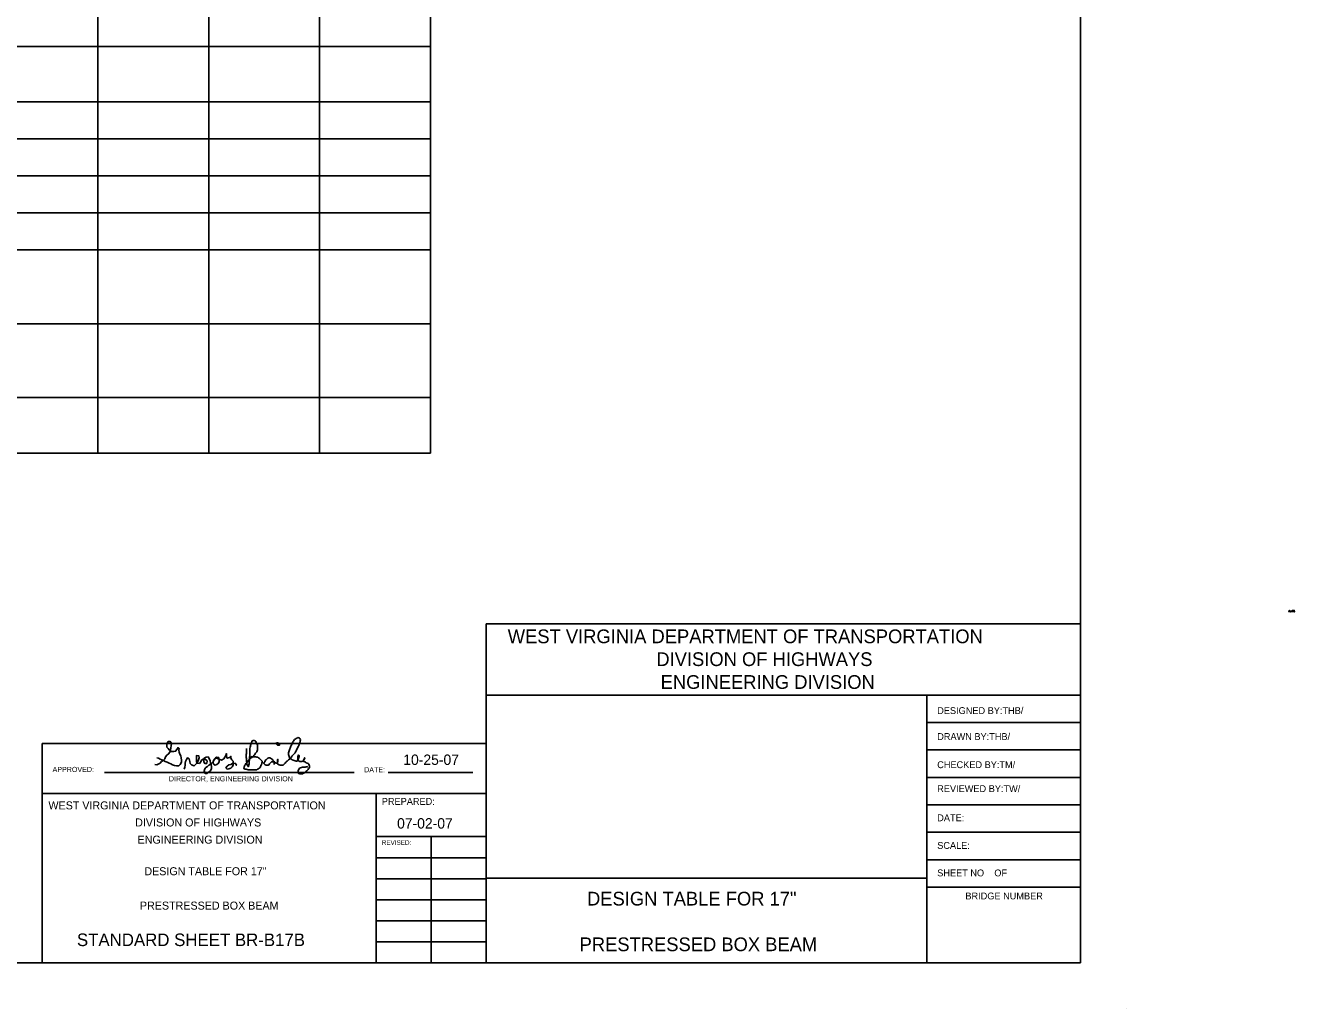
# Model space of a CAD drawing. Extents: x 762.3 to 791.9, y -1210.3 to -1192.2.
# Drawn here: x 780.44 to 791.88, y -1210.35 to -1201.48 of the extents above; entities that cross this region are included whole.
import ezdxf

# ---------------------------------------------------------------- set-up
doc = ezdxf.new("R2010")
doc.units = 0
doc.layers.add('Default', color=7, linetype='Continuous')
doc.layers.add('Level 1', color=7, linetype='Continuous')

msp = doc.modelspace()

# ---------------------------------------------------------------- linework, layer by layer
at = {"layer": 'Default'}
for p, q in [((789.954, -1192.61), (789.954, -1209.935)), ((781.091, -1202.169), (781.091, -1201.169)), ((782.091, -1202.169), (782.091, -1201.169)), ((783.091, -1202.169), (783.091, -1201.169)), ((784.091, -1202.169), (784.091, -1201.169)), ((764.508, -1201.669), (784.091, -1201.669)), ((764.508, -1202.169), (784.091, -1202.169)), ((781.091, -1205.336), (781.091, -1202.169)), ((782.091, -1205.336), (782.091, -1202.169)), ((783.091, -1205.336), (783.091, -1202.169)), ((784.091, -1205.336), (784.091, -1202.169)), ((766.258, -1202.502), (784.091, -1202.502)), ((766.258, -1202.836), (784.091, -1202.836)), ((764.508, -1203.169), (784.091, -1203.169)), ((766.258, -1203.502), (784.091, -1203.502)), ((766.258, -1204.169), (784.091, -1204.169)), ((764.508, -1204.836), (784.091, -1204.836)), ((764.508, -1205.336), (784.091, -1205.336)), ((789.954, -1206.875), (784.592, -1206.875)), ((784.592, -1206.875), (784.592, -1209.935)), ((784.592, -1206.941), (784.592, -1206.941)), ((789.954, -1206.941), (789.954, -1206.941)), ((788.568, -1207.519), (784.592, -1207.519)), ((788.568, -1207.519), (788.568, -1209.935)), ((789.954, -1207.519), (788.568, -1207.519)), ((789.954, -1207.766), (788.568, -1207.766)), ((784.592, -1207.955), (780.59, -1207.955)), ((780.59, -1207.955), (780.59, -1209.935)), ((784.592, -1207.955), (784.592, -1207.955)), ((789.954, -1208.014), (788.568, -1208.014)), ((781.152, -1208.216), (783.402, -1208.216)), ((783.71, -1208.216), (784.473, -1208.216)), ((789.954, -1208.261), (788.568, -1208.261)), ((783.602, -1208.408), (780.59, -1208.408)), ((783.602, -1208.408), (783.602, -1209.935)), ((784.592, -1208.408), (783.602, -1208.408)), ((789.954, -1208.509), (788.568, -1208.509)), ((784.592, -1208.796), (783.602, -1208.796)), ((784.097, -1208.796), (784.097, -1209.935)), ((789.954, -1208.756), (788.568, -1208.756)), ((784.592, -1208.986), (783.602, -1208.986)), ((789.954, -1209.004), (788.568, -1209.004)), ((784.592, -1209.176), (783.602, -1209.176)), ((788.568, -1209.169), (784.592, -1209.169)), ((789.954, -1209.251), (788.568, -1209.251)), ((784.592, -1209.365), (783.602, -1209.365)), ((784.592, -1209.555), (783.602, -1209.555)), ((784.592, -1209.745), (783.602, -1209.745)), ((789.954, -1209.935), (763.554, -1209.935)), ((784.592, -1209.935), (784.592, -1209.935)), ((784.592, -1209.935), (784.592, -1209.935)), ((789.954, -1209.911), (789.954, -1209.911)), ((789.954, -1209.935), (789.954, -1209.935)), ((790.367, -1210.347), (790.367, -1210.347))]:
    msp.add_line(p, q, dxfattribs=at)
at = {"layer": 'Level 1'}
for points in [[(791.83, -1206.764), (791.831, -1206.764), (791.831, -1206.764), (791.832, -1206.764), (791.832, -1206.763), (791.833, -1206.763), (791.834, -1206.762), (791.834, -1206.762), (791.834, -1206.761), (791.835, -1206.76), (791.835, -1206.76), (791.836, -1206.759), (791.836, -1206.758), (791.836, -1206.758), (791.836, -1206.757), (791.836, -1206.756), (791.835, -1206.756), (791.835, -1206.757), (791.834, -1206.757), (791.834, -1206.758), (791.835, -1206.759), (791.835, -1206.759), (791.836, -1206.76), (791.837, -1206.76), (791.837, -1206.76), (791.838, -1206.759), (791.838, -1206.758), (791.839, -1206.759), (791.838, -1206.759), (791.839, -1206.76), (791.839, -1206.761), (791.839, -1206.761), (791.839, -1206.762), (791.839, -1206.763), (791.839, -1206.763), (791.839, -1206.764), (791.838, -1206.765), (791.838, -1206.765), (791.837, -1206.764), (791.836, -1206.764), (791.836, -1206.764), (791.835, -1206.764), (791.834, -1206.763), (791.834, -1206.763), (791.833, -1206.763), (791.833, -1206.763), (791.832, -1206.762), (791.831, -1206.762), (791.831, -1206.762)], [(791.84, -1206.766), (791.841, -1206.765), (791.841, -1206.764), (791.841, -1206.764), (791.841, -1206.763), (791.841, -1206.762), (791.842, -1206.762), (791.842, -1206.762), (791.842, -1206.763), (791.842, -1206.764), (791.843, -1206.764), (791.844, -1206.765), (791.844, -1206.764), (791.845, -1206.764), (791.845, -1206.763), (791.845, -1206.763), (791.846, -1206.762), (791.845, -1206.761), (791.845, -1206.761), (791.845, -1206.762), (791.845, -1206.762), (791.845, -1206.763), (791.845, -1206.764), (791.846, -1206.764), (791.846, -1206.763), (791.846, -1206.763), (791.847, -1206.762), (791.848, -1206.762), (791.848, -1206.763), (791.848, -1206.764), (791.848, -1206.764), (791.847, -1206.763), (791.847, -1206.763), (791.847, -1206.762), (791.848, -1206.762), (791.849, -1206.762), (791.849, -1206.762), (791.849, -1206.763), (791.85, -1206.764), (791.85, -1206.764), (791.85, -1206.765), (791.85, -1206.766), (791.849, -1206.766), (791.849, -1206.767), (791.848, -1206.767), (791.848, -1206.767), (791.847, -1206.766), (791.848, -1206.766), (791.848, -1206.765), (791.848, -1206.765), (791.849, -1206.764), (791.85, -1206.764), (791.85, -1206.763), (791.851, -1206.763), (791.851, -1206.762), (791.852, -1206.762), (791.852, -1206.762), (791.853, -1206.762), (791.853, -1206.763), (791.852, -1206.764), (791.852, -1206.764), (791.851, -1206.764), (791.851, -1206.764), (791.85, -1206.763), (791.851, -1206.763), (791.851, -1206.762), (791.852, -1206.762), (791.853, -1206.762), (791.853, -1206.763), (791.854, -1206.762), (791.855, -1206.762), (791.855, -1206.761), (791.855, -1206.76), (791.855, -1206.761), (791.855, -1206.761), (791.855, -1206.762), (791.856, -1206.762), (791.857, -1206.761), (791.857, -1206.761), (791.857, -1206.762), (791.857, -1206.763), (791.857, -1206.763), (791.857, -1206.764), (791.857, -1206.764), (791.857, -1206.765), (791.857, -1206.765), (791.856, -1206.766), (791.855, -1206.766), (791.855, -1206.765), (791.855, -1206.765), (791.856, -1206.764), (791.857, -1206.764), (791.857, -1206.764), (791.858, -1206.764), (791.859, -1206.764), (791.859, -1206.764)], [(791.862, -1206.759), (791.862, -1206.759), (791.862, -1206.759), (791.862, -1206.76), (791.862, -1206.76), (791.862, -1206.76), (791.862, -1206.761), (791.862, -1206.761), (791.862, -1206.761), (791.862, -1206.762), (791.862, -1206.762), (791.862, -1206.762), (791.862, -1206.763), (791.862, -1206.763), (791.862, -1206.763), (791.862, -1206.764), (791.862, -1206.764), (791.862, -1206.764), (791.863, -1206.765), (791.863, -1206.765), (791.863, -1206.765), (791.863, -1206.764), (791.863, -1206.764), (791.863, -1206.764), (791.863, -1206.763), (791.863, -1206.763), (791.863, -1206.763), (791.863, -1206.762), (791.863, -1206.762), (791.863, -1206.762), (791.863, -1206.761), (791.863, -1206.761), (791.863, -1206.761), (791.863, -1206.76), (791.863, -1206.76), (791.863, -1206.76), (791.863, -1206.759), (791.863, -1206.759), (791.863, -1206.759), (791.863, -1206.758), (791.863, -1206.758), (791.864, -1206.758), (791.864, -1206.757), (791.864, -1206.757), (791.864, -1206.757), (791.864, -1206.756), (791.864, -1206.756), (791.864, -1206.756), (791.865, -1206.756), (791.865, -1206.756), (791.865, -1206.756), (791.865, -1206.757), (791.866, -1206.757), (791.866, -1206.757), (791.866, -1206.757), (791.866, -1206.758), (791.866, -1206.758), (791.866, -1206.758), (791.866, -1206.759), (791.866, -1206.759), (791.866, -1206.759), (791.866, -1206.76), (791.865, -1206.76), (791.865, -1206.76), (791.865, -1206.761), (791.865, -1206.761), (791.865, -1206.761), (791.865, -1206.761), (791.864, -1206.762), (791.864, -1206.762), (791.864, -1206.762), (791.863, -1206.762), (791.863, -1206.762), (791.863, -1206.763), (791.863, -1206.763), (791.862, -1206.763), (791.862, -1206.763), (791.862, -1206.764), (791.862, -1206.764), (791.862, -1206.764), (791.862, -1206.764), (791.861, -1206.765), (791.861, -1206.765), (791.861, -1206.765), (791.861, -1206.766), (791.862, -1206.766), (791.862, -1206.766), (791.862, -1206.766), (791.863, -1206.766), (791.863, -1206.766), (791.863, -1206.766), (791.864, -1206.766), (791.864, -1206.766), (791.864, -1206.766), (791.865, -1206.766), (791.865, -1206.766), (791.865, -1206.766), (791.866, -1206.766), (791.866, -1206.766), (791.866, -1206.766), (791.867, -1206.765), (791.867, -1206.765), (791.867, -1206.765), (791.867, -1206.765), (791.867, -1206.764), (791.867, -1206.764), (791.867, -1206.764), (791.867, -1206.763), (791.867, -1206.763), (791.867, -1206.763), (791.867, -1206.763), (791.867, -1206.762), (791.867, -1206.762), (791.866, -1206.762), (791.866, -1206.762), (791.866, -1206.762), (791.865, -1206.762), (791.865, -1206.762), (791.865, -1206.762), (791.864, -1206.762), (791.864, -1206.762), (791.864, -1206.761), (791.864, -1206.761)], [(791.872, -1206.764), (791.872, -1206.764), (791.872, -1206.763), (791.872, -1206.763), (791.871, -1206.763), (791.871, -1206.763), (791.871, -1206.762), (791.871, -1206.762), (791.87, -1206.762), (791.87, -1206.762), (791.87, -1206.762), (791.869, -1206.762), (791.869, -1206.762), (791.869, -1206.762), (791.869, -1206.763), (791.869, -1206.763), (791.868, -1206.763), (791.868, -1206.763), (791.868, -1206.764), (791.868, -1206.764), (791.869, -1206.764), (791.869, -1206.764), (791.869, -1206.764), (791.87, -1206.764), (791.87, -1206.764), (791.87, -1206.764), (791.87, -1206.764), (791.871, -1206.763), (791.871, -1206.763), (791.871, -1206.763), (791.872, -1206.763), (791.872, -1206.763), (791.872, -1206.764), (791.872, -1206.764), (791.873, -1206.764), (791.873, -1206.763), (791.873, -1206.763), (791.873, -1206.763), (791.873, -1206.762), (791.873, -1206.763), (791.873, -1206.763), (791.873, -1206.763), (791.873, -1206.764), (791.873, -1206.764), (791.873, -1206.764), (791.873, -1206.764), (791.874, -1206.764), (791.874, -1206.764), (791.874, -1206.764), (791.875, -1206.764), (791.875, -1206.764), (791.875, -1206.764), (791.876, -1206.764), (791.876, -1206.763), (791.876, -1206.763), (791.876, -1206.763), (791.876, -1206.763), (791.877, -1206.763), (791.877, -1206.762), (791.877, -1206.762), (791.877, -1206.762)], [(791.873, -1206.757), (791.873, -1206.757), (791.873, -1206.757), (791.873, -1206.758), (791.874, -1206.757), (791.874, -1206.757), (791.873, -1206.757), (791.873, -1206.757), (791.873, -1206.757), (791.872, -1206.757), (791.872, -1206.757)], [(791.878, -1206.762), (791.878, -1206.762), (791.878, -1206.761), (791.878, -1206.761), (791.878, -1206.761), (791.879, -1206.761), (791.879, -1206.76), (791.879, -1206.76), (791.879, -1206.76), (791.879, -1206.759), (791.88, -1206.759), (791.88, -1206.759), (791.88, -1206.759), (791.88, -1206.758), (791.88, -1206.758), (791.88, -1206.758), (791.88, -1206.757), (791.88, -1206.757), (791.881, -1206.757), (791.881, -1206.756), (791.881, -1206.756), (791.881, -1206.756), (791.881, -1206.755), (791.881, -1206.755), (791.88, -1206.755), (791.88, -1206.755), (791.88, -1206.755), (791.879, -1206.755), (791.879, -1206.755), (791.879, -1206.756), (791.879, -1206.756), (791.878, -1206.756), (791.878, -1206.756), (791.878, -1206.757), (791.878, -1206.757), (791.878, -1206.757), (791.878, -1206.758), (791.878, -1206.758), (791.877, -1206.758), (791.877, -1206.759), (791.877, -1206.759), (791.877, -1206.759), (791.877, -1206.759), (791.877, -1206.76), (791.877, -1206.76), (791.877, -1206.76), (791.877, -1206.761), (791.877, -1206.761), (791.877, -1206.761), (791.877, -1206.762), (791.877, -1206.762), (791.877, -1206.762), (791.878, -1206.762), (791.878, -1206.763), (791.878, -1206.763), (791.879, -1206.763), (791.879, -1206.763), (791.879, -1206.763), (791.88, -1206.763), (791.88, -1206.763), (791.88, -1206.762), (791.88, -1206.762), (791.88, -1206.762), (791.88, -1206.761), (791.88, -1206.761), (791.88, -1206.761), (791.88, -1206.761), (791.88, -1206.762), (791.88, -1206.762), (791.88, -1206.762), (791.88, -1206.763), (791.88, -1206.763), (791.88, -1206.763), (791.881, -1206.763), (791.881, -1206.763), (791.881, -1206.763), (791.882, -1206.763), (791.882, -1206.763), (791.882, -1206.763), (791.882, -1206.762), (791.882, -1206.762), (791.882, -1206.762), (791.882, -1206.762), (791.882, -1206.763), (791.882, -1206.763), (791.882, -1206.763), (791.883, -1206.763), (791.883, -1206.764), (791.883, -1206.764), (791.884, -1206.764), (791.884, -1206.764), (791.884, -1206.764), (791.884, -1206.765), (791.884, -1206.765), (791.884, -1206.765), (791.884, -1206.766), (791.883, -1206.766), (791.883, -1206.766), (791.883, -1206.766), (791.883, -1206.767), (791.883, -1206.767), (791.882, -1206.767), (791.882, -1206.767), (791.882, -1206.767), (791.881, -1206.767), (791.881, -1206.767), (791.881, -1206.767), (791.88, -1206.767), (791.88, -1206.767), (791.88, -1206.767), (791.88, -1206.766), (791.88, -1206.766), (791.88, -1206.766), (791.881, -1206.765), (791.881, -1206.765), (791.881, -1206.765), (791.882, -1206.765), (791.882, -1206.765), (791.882, -1206.765), (791.883, -1206.765), (791.883, -1206.765), (791.883, -1206.765), (791.883, -1206.765)], [(781.605, -1208.144), (781.624, -1208.148), (781.636, -1208.142), (781.653, -1208.132), (781.665, -1208.119), (781.681, -1208.109), (781.695, -1208.095), (781.703, -1208.076), (781.715, -1208.062), (781.729, -1208.049), (781.74, -1208.033), (781.748, -1208.016), (781.751, -1207.995), (781.754, -1207.976), (781.756, -1207.957), (781.745, -1207.938), (781.727, -1207.938), (781.718, -1207.952), (781.715, -1207.97), (781.715, -1207.989), (781.727, -1208.001), (781.738, -1208.017), (781.754, -1208.027), (781.775, -1208.028), (781.792, -1208.025), (781.804, -1208.011), (781.815, -1207.993), (781.824, -1208), (781.821, -1208.017), (781.826, -1208.035), (781.832, -1208.051), (781.839, -1208.067), (781.842, -1208.086), (781.845, -1208.105), (781.845, -1208.124), (781.834, -1208.144), (781.821, -1208.157), (781.8, -1208.157), (781.784, -1208.153), (781.765, -1208.148), (781.749, -1208.138), (781.734, -1208.134), (781.716, -1208.125), (781.699, -1208.119), (781.684, -1208.109), (781.668, -1208.103), (781.653, -1208.097), (781.638, -1208.087), (781.622, -1208.084)], [(782.433, -1208.001), (782.433, -1208.01), (782.433, -1208.019), (782.433, -1208.028), (782.433, -1208.037), (782.432, -1208.046), (782.43, -1208.055), (782.43, -1208.063), (782.43, -1208.072), (782.43, -1208.081), (782.431, -1208.09), (782.432, -1208.098), (782.432, -1208.107), (782.433, -1208.116), (782.434, -1208.125), (782.435, -1208.134), (782.436, -1208.143), (782.438, -1208.152), (782.444, -1208.158), (782.449, -1208.165), (782.451, -1208.156), (782.454, -1208.148), (782.457, -1208.14), (782.457, -1208.131), (782.457, -1208.122), (782.457, -1208.113), (782.458, -1208.105), (782.458, -1208.096), (782.459, -1208.087), (782.46, -1208.078), (782.461, -1208.07), (782.461, -1208.061), (782.461, -1208.052), (782.461, -1208.043), (782.461, -1208.035), (782.461, -1208.026), (782.461, -1208.017), (782.461, -1208.009), (782.463, -1208), (782.464, -1207.99), (782.467, -1207.981), (782.469, -1207.973), (782.47, -1207.964), (782.473, -1207.956), (782.476, -1207.948), (782.48, -1207.94), (782.484, -1207.932), (782.492, -1207.929), (782.501, -1207.93), (782.51, -1207.932), (782.515, -1207.939), (782.519, -1207.947), (782.524, -1207.954), (782.528, -1207.962), (782.53, -1207.97), (782.53, -1207.979), (782.53, -1207.988), (782.53, -1207.997), (782.53, -1208.005), (782.53, -1208.014), (782.529, -1208.023), (782.524, -1208.03), (782.518, -1208.036), (782.512, -1208.042), (782.509, -1208.05), (782.504, -1208.057), (782.499, -1208.064), (782.496, -1208.072), (782.489, -1208.077), (782.481, -1208.081), (782.474, -1208.086), (782.466, -1208.091), (782.46, -1208.097), (782.453, -1208.103), (782.449, -1208.11), (782.442, -1208.116), (782.437, -1208.123), (782.433, -1208.13), (782.426, -1208.137), (782.422, -1208.144), (782.418, -1208.152), (782.414, -1208.16), (782.41, -1208.167), (782.409, -1208.176), (782.412, -1208.184), (782.42, -1208.187), (782.429, -1208.188), (782.437, -1208.191), (782.446, -1208.192), (782.455, -1208.193), (782.464, -1208.193), (782.473, -1208.193), (782.482, -1208.193), (782.491, -1208.193), (782.499, -1208.193), (782.508, -1208.193), (782.517, -1208.193), (782.526, -1208.193), (782.532, -1208.187), (782.54, -1208.183), (782.547, -1208.179), (782.554, -1208.172), (782.557, -1208.164), (782.561, -1208.156), (782.565, -1208.149), (782.569, -1208.141), (782.571, -1208.133), (782.573, -1208.124), (782.573, -1208.115), (782.567, -1208.109), (782.561, -1208.103), (782.554, -1208.097), (782.549, -1208.09), (782.541, -1208.085), (782.533, -1208.08), (782.524, -1208.078), (782.515, -1208.077), (782.507, -1208.075), (782.497, -1208.075), (782.488, -1208.075), (782.479, -1208.075), (782.47, -1208.074), (782.47, -1208.074)], [(782.705, -1207.955), (782.705, -1207.964), (782.712, -1207.97), (782.72, -1207.972), (782.729, -1207.971), (782.731, -1207.962), (782.724, -1207.957), (782.718, -1207.95), (782.709, -1207.95), (782.701, -1207.954), (782.701, -1207.959)], [(782.833, -1208.086), (782.837, -1208.078), (782.842, -1208.071), (782.847, -1208.064), (782.852, -1208.058), (782.86, -1208.053), (782.865, -1208.047), (782.87, -1208.039), (782.874, -1208.031), (782.879, -1208.023), (782.884, -1208.015), (782.887, -1208.007), (782.892, -1207.998), (782.896, -1207.989), (782.9, -1207.981), (782.903, -1207.973), (782.906, -1207.965), (782.91, -1207.957), (782.912, -1207.948), (782.915, -1207.94), (782.917, -1207.931), (782.918, -1207.923), (782.917, -1207.914), (782.911, -1207.908), (782.903, -1207.904), (782.895, -1207.903), (782.887, -1207.908), (782.879, -1207.912), (782.871, -1207.916), (782.865, -1207.921), (782.86, -1207.928), (782.856, -1207.935), (782.849, -1207.942), (782.848, -1207.95), (782.844, -1207.958), (782.841, -1207.966), (782.836, -1207.974), (782.833, -1207.981), (782.829, -1207.989), (782.827, -1207.997), (782.822, -1208.005), (782.821, -1208.013), (782.817, -1208.022), (782.814, -1208.031), (782.811, -1208.039), (782.811, -1208.047), (782.811, -1208.056), (782.813, -1208.065), (782.817, -1208.073), (782.82, -1208.082), (782.824, -1208.09), (782.83, -1208.095), (782.838, -1208.098), (782.845, -1208.104), (782.854, -1208.105), (782.862, -1208.11), (782.87, -1208.113), (782.879, -1208.114), (782.888, -1208.114), (782.893, -1208.107), (782.898, -1208.1), (782.902, -1208.091), (782.905, -1208.082), (782.906, -1208.074), (782.908, -1208.064), (782.902, -1208.059), (782.898, -1208.067), (782.895, -1208.075), (782.895, -1208.084), (782.895, -1208.093), (782.895, -1208.102), (782.898, -1208.11), (782.906, -1208.115), (782.914, -1208.118), (782.923, -1208.119), (782.932, -1208.119), (782.94, -1208.116), (782.945, -1208.108), (782.95, -1208.102), (782.954, -1208.093), (782.957, -1208.084), (782.953, -1208.093), (782.949, -1208.101), (782.946, -1208.109), (782.949, -1208.117), (782.957, -1208.121), (782.965, -1208.125), (782.971, -1208.131), (782.98, -1208.133), (782.988, -1208.136), (782.994, -1208.143), (782.997, -1208.151), (783, -1208.159), (783, -1208.167), (782.999, -1208.176), (782.992, -1208.182), (782.988, -1208.189), (782.981, -1208.196), (782.976, -1208.203), (782.968, -1208.209), (782.962, -1208.214), (782.954, -1208.219), (782.946, -1208.224), (782.939, -1208.229), (782.929, -1208.229), (782.921, -1208.23), (782.912, -1208.23), (782.904, -1208.226), (782.899, -1208.218), (782.898, -1208.21), (782.898, -1208.201), (782.901, -1208.192), (782.906, -1208.184), (782.911, -1208.178), (782.919, -1208.175), (782.927, -1208.171), (782.936, -1208.17), (782.945, -1208.17), (782.953, -1208.168), (782.962, -1208.168), (782.971, -1208.167), (782.98, -1208.165), (782.984, -1208.164)], [(781.871, -1208.187), (781.875, -1208.169), (781.878, -1208.152), (781.88, -1208.134), (781.883, -1208.117), (781.89, -1208.099), (781.9, -1208.085), (781.914, -1208.095), (781.922, -1208.119), (781.925, -1208.136), (781.936, -1208.149), (781.959, -1208.158), (781.972, -1208.146), (781.983, -1208.132), (781.993, -1208.118), (781.999, -1208.102), (782.005, -1208.085), (782.003, -1208.067), (781.98, -1208.064), (781.98, -1208.082), (781.98, -1208.099), (781.982, -1208.117), (781.988, -1208.133), (782.008, -1208.135), (782.019, -1208.122), (782.025, -1208.105), (782.041, -1208.098), (782.058, -1208.098), (782.078, -1208.113), (782.073, -1208.135), (782.055, -1208.136), (782.046, -1208.122), (782.046, -1208.104), (782.052, -1208.086), (782.067, -1208.078), (782.085, -1208.075), (782.099, -1208.096), (782.104, -1208.113), (782.108, -1208.13), (782.114, -1208.147), (782.116, -1208.164), (782.116, -1208.183), (782.104, -1208.204), (782.09, -1208.215), (782.075, -1208.225), (782.058, -1208.226), (782.05, -1208.202), (782.055, -1208.185), (782.066, -1208.172), (782.079, -1208.163), (782.092, -1208.152), (782.113, -1208.14), (782.131, -1208.121), (782.137, -1208.107), (782.149, -1208.091), (782.159, -1208.078), (782.182, -1208.082), (782.186, -1208.1), (782.186, -1208.117), (782.18, -1208.134), (782.166, -1208.144), (782.15, -1208.15), (782.135, -1208.142), (782.131, -1208.125), (782.135, -1208.109), (782.146, -1208.094), (782.162, -1208.088), (782.185, -1208.098), (782.208, -1208.106), (782.228, -1208.094), (782.238, -1208.08), (782.247, -1208.064), (782.253, -1208.047), (782.253, -1208.055), (782.251, -1208.073), (782.259, -1208.089), (782.279, -1208.083), (782.29, -1208.07), (782.292, -1208.071), (782.29, -1208.088), (782.299, -1208.104), (782.312, -1208.116), (782.313, -1208.133), (782.313, -1208.151), (782.303, -1208.165), (782.29, -1208.177), (782.274, -1208.184), (782.257, -1208.188), (782.247, -1208.175), (782.258, -1208.16), (782.273, -1208.149), (782.29, -1208.146), (782.305, -1208.136), (782.329, -1208.132), (782.342, -1208.152), (782.344, -1208.151)], [(782.681, -1208.144), (782.682, -1208.135), (782.682, -1208.126), (782.682, -1208.117), (782.675, -1208.111), (782.669, -1208.105), (782.664, -1208.098), (782.657, -1208.093), (782.65, -1208.088), (782.642, -1208.085), (782.633, -1208.085), (782.624, -1208.088), (782.618, -1208.094), (782.611, -1208.099), (782.604, -1208.105), (782.6, -1208.112), (782.596, -1208.12), (782.592, -1208.127), (782.588, -1208.135), (782.594, -1208.141), (782.6, -1208.148), (782.609, -1208.15), (782.618, -1208.15), (782.627, -1208.15), (782.635, -1208.147), (782.64, -1208.14), (782.646, -1208.133), (782.651, -1208.126), (782.659, -1208.121), (782.669, -1208.121), (782.678, -1208.122), (782.686, -1208.125), (782.694, -1208.129), (782.701, -1208.133), (782.71, -1208.133), (782.712, -1208.125), (782.715, -1208.116), (782.716, -1208.106), (782.716, -1208.098), (782.712, -1208.105), (782.711, -1208.114), (782.711, -1208.123), (782.711, -1208.132), (782.712, -1208.14), (782.72, -1208.144), (782.728, -1208.149), (782.736, -1208.152), (782.745, -1208.152), (782.754, -1208.152), (782.763, -1208.151), (782.77, -1208.146), (782.774, -1208.138), (782.781, -1208.133), (782.786, -1208.125), (782.792, -1208.119), (782.799, -1208.114), (782.805, -1208.108), (782.812, -1208.102), (782.819, -1208.097), (782.826, -1208.092), (782.831, -1208.086)]]:
    msp.add_lwpolyline(points, dxfattribs=at)

# ---------------------------------------------------------------- texts
at = {"layer": 'Default'}
for s, height, p in [('WEST VIRGINIA DEPARTMENT OF TRANSPORTATION', 0.12375, (784.788, -1207.051)), ('DIVISION OF HIGHWAYS', 0.12375, (786.128, -1207.257)), ('ENGINEERING DIVISION', 0.12375, (786.167, -1207.463)), ('DESIGNED BY:THB/', 0.06187, (788.661, -1207.69)), ('DRAWN BY:THB/', 0.06187, (788.661, -1207.924)), ('10-25-07', 0.0938, (783.846, -1208.149)), ('CHECKED BY:TM/', 0.06187, (788.661, -1208.178)), ('APPROVED:                                                  ', 0.04641, (780.683, -1208.213)), ('DATE:', 0.0464, (783.493, -1208.216)), ('DIRECTOR, ENGINEERING DIVISION', 0.04641, (781.732, -1208.297)), ('REVIEWED BY:TW/', 0.06187, (788.661, -1208.394)), ('PREPARED:', 0.0619, (783.652, -1208.509)), ('WEST VIRGINIA DEPARTMENT OF TRANSPORTATION', 0.07219, (780.646, -1208.55)), ('DIVISION OF HIGHWAYS', 0.07219, (781.428, -1208.704)), ('07-02-07', 0.0938, (783.79, -1208.723)), ('DATE:', 0.0619, (788.661, -1208.657)), ('ENGINEERING DIVISION', 0.07219, (781.45, -1208.859)), ('REVISED:', 0.0413, (783.652, -1208.87)), ('SCALE:', 0.0619, (788.661, -1208.906)), ('DESIGN TABLE FOR 17"', 0.07219, (781.511, -1209.144)), ('SHEET NO    OF', 0.06187, (788.661, -1209.154)), ('DESIGN TABLE FOR 17"', 0.12375, (785.503, -1209.417)), ('BRIDGE NUMBER', 0.06187, (788.915, -1209.362)), ('PRESTRESSED BOX BEAM', 0.07219, (781.471, -1209.454)), ('STANDARD SHEET BR-B17B', 0.11344, (780.903, -1209.783)), ('PRESTRESSED BOX BEAM', 0.12375, (785.436, -1209.829))]:
    msp.add_text(s, height=height, dxfattribs=at).set_placement(p)

doc.saveas('drawing.dxf')
